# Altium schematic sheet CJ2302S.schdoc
size 127 x 101 mm
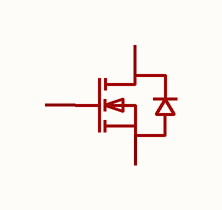
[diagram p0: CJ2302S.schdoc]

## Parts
Q?  cj2302s  [SOT-23_L2.9-W1.3-P1.90-LS2.4-BR]  (value not drawn)

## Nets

Not connected (* = marked no-connect by the designer): Q? 1(G) 2(S) 3(D)

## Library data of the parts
Q? = cj2302s: 数量:1个N沟道;漏源电压(Vdss):20V;连续漏极电流(Id):2.1A;导通电阻(RDS(on)):60mΩ@4.5V;耗散功率(Pd):350mW;阈值电压(Vgs(th)):650mV;; Manufacturer: CJ(江苏长电/长晶); AddInBom: yes; ModelId: c62791f0466c4ae2a892c056b845b0ca; ModelName: SOT-23-3P_L2.9-W1.3-H1.0-LS2.4-P0.95; ModelTransform: 98.64468,114.173,0,180,0,0,0.001,-0.002,0; Number: 1个N沟道; Drain to Source Voltage: 20V; Current - Continuous Drain(Id): 2.1A; Pd - Power Dissipation: 350mW; Gate Threshold Voltage (Vgs(th)): 650mV; Gate Charge(Qg): 10nC@4.5V; Input Capacitance(Ciss): 300pF; Reverse Transfer Capacitance (Crss@Vds): 80pF; Type: N沟道; Output Capacitance(Coss): 120pF; Vgs: ±8V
